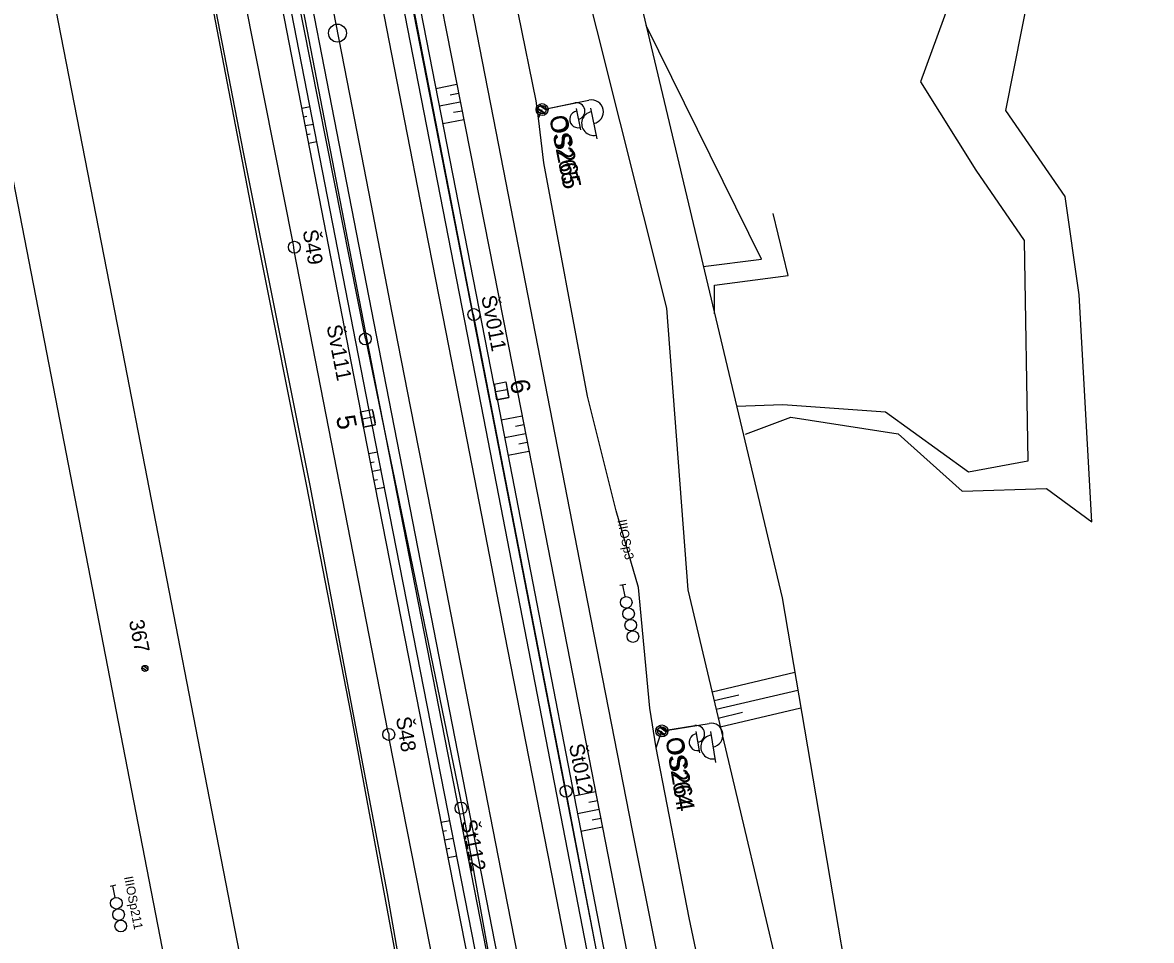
# Model space of a CAD drawing. Extents: x -545967 to -545044, y -1122650 to -1118491.
# Drawn here: x -545804.3 to -545710, y -1118963 to -1118886.3 of the extents above; entities that cross this region are included whole.
import ezdxf

# ---------------------------------------------------------------- set-up
doc = ezdxf.new("R2010")
doc.units = 0
for name, color, linetype in [('Vrstva 1', 7, 'Continuous'), ('Vrstva 1 - Koleje', 7, 'Continuous'), ('Vrstva 11', 7, 'Continuous'), ('Vrstva 11 - Trakce', 7, 'Continuous'), ('Vrstva 12 - Trakce zaklady', 7, 'Continuous'), ('Vrstva 19 - Staniceni', 7, 'Continuous'), ('Vrstva 25', 7, 'Continuous'), ('Vrstva 25 - silnoproud prvky', 7, 'Continuous'), ('Vrstva 26', 7, 'Continuous'), ('Vrstva 26 - silnoproud', 7, 'Continuous'), ('Vrstva 28 - zabzar', 7, 'Continuous'), ('Vrstva 32', 7, 'Continuous'), ('Vrstva 4 - Teren - stezky - prechody - plochy', 7, 'Continuous'), ('Vrstva 43', 7, 'Continuous'), ('Vrstva 44', 7, 'Continuous'), ('Vrstva 48', 7, 'Continuous'), ('Vrstva 49', 7, 'Continuous'), ('Vrstva 6', 7, 'Continuous'), ('Vrstva 62', 7, 'Continuous')]:
    doc.layers.add(name, color=color, linetype=linetype)

msp = doc.modelspace()

# ---------------------------------------------------------------- linework, layer by layer
at = {"layer": 'Vrstva 1'}
for points in [[(-545803.343, -1118697.361), (-545802.529, -1118701.559), (-545796.372, -1118733.137), (-545788.892, -1118771.626), (-545784.123, -1118796.192), (-545777.723, -1118829.089), (-545771.163, -1118862.699), (-545764.792, -1118895.381), (-545757.603, -1118932.309), (-545753.441, -1118953.648), (-545749.904, -1118971.286), (-545746.403, -1118987.4), (-545742.64, -1119003.664), (-545739.307, -1119017.411), (-545735.997, -1119030.103), (-545730.526, -1119049.438)], [(-545838.408, -1118714.766), (-545838.264, -1118718.348), (-545837.486, -1118728.28), (-545836.887, -1118733.389), (-545834.73, -1118746.875), (-545830.836, -1118767.188), (-545826.73, -1118788.319), (-545823.138, -1118806.831), (-545818.076, -1118832.894), (-545813.108, -1118858.452), (-545808.531, -1118881.987), (-545803.057, -1118910.121), (-545797.597, -1118938.248), (-545792.143, -1118966.396), (-545787.423, -1118990.652), (-545782.57, -1119015.553), (-545777.212, -1119042.997), (-545771.689, -1119071.297)], [(-545838.408, -1118714.766), (-545838.264, -1118718.348), (-545837.486, -1118728.28), (-545836.887, -1118733.389), (-545834.73, -1118746.875), (-545830.836, -1118767.188), (-545826.73, -1118788.319), (-545823.138, -1118806.831), (-545818.076, -1118832.894), (-545813.108, -1118858.452), (-545808.531, -1118881.987), (-545803.057, -1118910.121), (-545797.597, -1118938.248), (-545792.143, -1118966.396), (-545787.423, -1118990.652), (-545782.57, -1119015.553), (-545777.212, -1119042.997), (-545771.689, -1119071.297)], [(-545833.035, -1118722.987), (-545832.612, -1118725.218), (-545828.16, -1118748.155), (-545821.787, -1118781.064), (-545814.8, -1118816.973), (-545807.184, -1118856.232), (-545801.349, -1118886.259), (-545795.986, -1118913.812), (-545789.887, -1118945.221), (-545784.095, -1118975.016), (-545776.352, -1119014.883), (-545771.025, -1119042.195)]]:
    msp.add_lwpolyline(points, dxfattribs=at)
at = {"layer": 'Vrstva 1 - Koleje'}
for points in [[(-545789.005, -1118830.866), (-545787.094, -1118840.68), (-545785.112, -1118850.841), (-545782.605, -1118863.702), (-545780.708, -1118873.411), (-545778.842, -1118882.982), (-545777.033, -1118892.261), (-545775.242, -1118901.451), (-545773.471, -1118910.538), (-545771.912, -1118918.507), (-545770.23, -1118927.147), (-545768.195, -1118937.605), (-545766.358, -1118947.027), (-545764.382, -1118957.157), (-545762.439, -1118967.113)], [(-545783.856, -1118835.888), (-545781.902, -1118845.893), (-545780.09, -1118855.197), (-545779.231, -1118859.597), (-545777.534, -1118868.303), (-545775.637, -1118878.025), (-545773.736, -1118887.804), (-545771.983, -1118896.787), (-545770.701, -1118903.363), (-545768.985, -1118912.147), (-545767.842, -1118918.004), (-545766.003, -1118927.456), (-545764.066, -1118937.395), (-545762.038, -1118947.792), (-545760.159, -1118957.414), (-545758.172, -1118967.592)]]:
    msp.add_lwpolyline(points, dxfattribs=at)
at = {"layer": 'Vrstva 11'}
for p, q in [((-545793.97, -1118940.46), (-545794.348, -1118940.204)), ((-545793.862, -1118940.306), (-545794.246, -1118940.047))]:
    msp.add_line(p, q, dxfattribs=at)
msp.add_circle((-545794.104, -1118940.251), 0.25, dxfattribs=at)
at = {"layer": 'Vrstva 11 - Trakce'}
for p, q in [((-545763.943, -1118916.485), (-545763.763, -1118917.469)), ((-545764.927, -1118916.665), (-545764.747, -1118917.649)), ((-545763.853, -1118916.977), (-545764.837, -1118917.157)), ((-545776.046, -1118918.952), (-545775.85, -1118919.932)), ((-545774.968, -1118919.246), (-545775.948, -1118919.442)), ((-545775.066, -1118918.756), (-545774.87, -1118919.736))]:
    msp.add_line(p, q, dxfattribs=at)
at = {"layer": 'Vrstva 12 - Trakce zaklady'}
for p, q in [((-545764.942, -1118916.501), (-545763.958, -1118916.32)), ((-545764.703, -1118917.803), (-545763.719, -1118917.622)), ((-545776.104, -1118918.814), (-545775.123, -1118918.618)), ((-545775.848, -1118920.094), (-545774.867, -1118919.898))]:
    msp.add_line(p, q, dxfattribs=at)
for points in [[(-545764.703, -1118917.803), (-545764.942, -1118916.501), (-545763.958, -1118916.32), (-545763.719, -1118917.622), (-545764.703, -1118917.803)], [(-545764.942, -1118916.501), (-545764.942, -1118916.501), (-545764.703, -1118917.803), (-545764.703, -1118917.803)], [(-545775.123, -1118918.618), (-545774.867, -1118919.898), (-545775.848, -1118920.094), (-545776.104, -1118918.814), (-545775.123, -1118918.618)], [(-545776.104, -1118918.814), (-545776.104, -1118918.814), (-545775.848, -1118920.094), (-545775.848, -1118920.094)], [(-545775.123, -1118918.618), (-545775.123, -1118918.618), (-545774.867, -1118919.898), (-545774.867, -1118919.898)]]:
    msp.add_lwpolyline(points, dxfattribs=at)
at = {"layer": 'Vrstva 19 - Staniceni'}
msp.add_circle((-545778.025, -1118887.174), 0.75, dxfattribs=at)
at = {"layer": 'Vrstva 25'}
for p, q in [((-545760.45, -1118893.462), (-545757.021, -1118892.763)), ((-545761.416, -1118893.415), (-545760.617, -1118893.943)), ((-545761.179, -1118893.123), (-545760.445, -1118893.608)), ((-545756.881, -1118893.449), (-545756.362, -1118895.997)), ((-545750.441, -1118945.401), (-545746.986, -1118944.844)), ((-545751.404, -1118945.315), (-545750.628, -1118945.875)), ((-545751.155, -1118945.032), (-545750.442, -1118945.547)), ((-545746.875, -1118945.536), (-545746.461, -1118948.102))]:
    msp.add_line(p, q, dxfattribs=at)
for centre in [(-545760.94, -1118893.562), (-545760.94, -1118893.562), (-545750.935, -1118945.481), (-545750.935, -1118945.481)]:
    msp.add_circle(centre, 0.5, dxfattribs=at)
for centre, start, end in [((-545756.821, -1118893.743), 281.52003, 101.52003), ((-545756.633, -1118894.725), 100.81745, 282.2226), ((-545746.827, -1118945.832), 279.15692, 99.15692), ((-545746.68, -1118946.821), 98.45434, 279.85949)]:
    msp.add_arc(centre, 1, start, end, dxfattribs=at)
at = {"layer": 'Vrstva 25 - silnoproud prvky'}
for p, q in [((-545760.597, -1118893.492), (-545758.196, -1118893.003)), ((-545761.273, -1118893.459), (-545760.714, -1118893.829)), ((-545761.107, -1118893.255), (-545760.593, -1118893.594)), ((-545758.099, -1118893.483), (-545757.735, -1118895.266)), ((-545751.264, -1118945.365), (-545750.72, -1118945.757)), ((-545751.089, -1118945.167), (-545750.59, -1118945.527)), ((-545750.589, -1118945.425), (-545748.171, -1118945.035)), ((-545748.093, -1118945.519), (-545747.803, -1118947.316))]:
    msp.add_line(p, q, dxfattribs=at)
for centre in [(-545760.94, -1118893.562), (-545750.935, -1118945.481)]:
    msp.add_circle(centre, 0.35, dxfattribs=at)
for centre, start, end in [((-545758.057, -1118893.689), 281.52003, 101.52003), ((-545757.925, -1118894.376), 100.81745, 282.2226), ((-545747.956, -1118946.419), 98.45434, 279.85949), ((-545748.059, -1118945.726), 279.15692, 99.15692)]:
    msp.add_arc(centre, 0.7, start, end, dxfattribs=at)
at = {"layer": 'Vrstva 26'}
for points in [[(-545746.037, -1118973.539), (-545748.64, -1118961.097), (-545751.402, -1118946.894), (-545751.937, -1118943.575), (-545752.873, -1118933.506), (-545754.741, -1118927.082), (-545757.146, -1118917.51), (-545760.799, -1118898.018), (-545761.246, -1118894.282), (-545761.421, -1118892.823), (-545762.895, -1118885.591), (-545764.903, -1118877.023), (-545767.229, -1118863.082), (-545767.317, -1118860.995), (-545767.592, -1118859.454), (-545769.02, -1118853.189), (-545770.747, -1118842.19), (-545771.097, -1118840.383), (-545773.141, -1118830.925)], [(-545761.246, -1118894.282), (-545760.94, -1118893.562)], [(-545751.402, -1118946.894), (-545750.935, -1118945.481)]]:
    msp.add_lwpolyline(points, dxfattribs=at)
at = {"layer": 'Vrstva 26 - silnoproud'}
for points in [[(-545800.897, -1118821.514), (-545796.684, -1118843.318), (-545791.187, -1118870.631), (-545788.655, -1118883.96), (-545784.722, -1118904.395), (-545780.641, -1118924.894), (-545776.901, -1118944.085), (-545772.527, -1118967.671), (-545767.712, -1118991.461), (-545763.383, -1119013.326), (-545759.751, -1119031.811), (-545755.576, -1119054.337), (-545752.321, -1119069.685), (-545748.72, -1119088.787), (-545745.498, -1119105.777)], [(-545746.037, -1118973.539), (-545748.64, -1118961.097), (-545751.402, -1118946.894), (-545751.937, -1118943.575), (-545752.873, -1118933.506), (-545754.741, -1118927.082), (-545757.146, -1118917.51), (-545760.799, -1118898.018), (-545761.246, -1118894.282), (-545761.421, -1118892.823), (-545762.895, -1118885.591), (-545764.903, -1118877.023), (-545767.229, -1118863.082), (-545767.317, -1118860.995), (-545767.592, -1118859.454), (-545769.02, -1118853.189), (-545770.747, -1118842.19), (-545771.097, -1118840.383), (-545773.141, -1118830.925)], [(-545761.246, -1118894.282), (-545760.94, -1118893.562)], [(-545751.402, -1118946.894), (-545750.935, -1118945.481)]]:
    msp.add_lwpolyline(points, dxfattribs=at)
at = {"layer": 'Vrstva 28 - zabzar'}
msp.add_lwpolyline([(-545759.72, -1119031.91), (-545759.89, -1119030.77), (-545763.23, -1119013.33), (-545766.25, -1118997.62), (-545768.86, -1118984.55), (-545771, -1118974.69), (-545771.8, -1118970.9), (-545773.86, -1118959.07), (-545776.3, -1118946.17), (-545780.31, -1118924.98), (-545785.87, -1118897.11), (-545790.99, -1118870.65), (-545796.29, -1118843.25), (-545799.19, -1118827.63), (-545805.85, -1118794.17), (-545808.2, -1118783.5), (-545812.82, -1118758.82), (-545816.62, -1118739.16), (-545820.43, -1118719.58), (-545822.89, -1118707.67), (-545825.23, -1118696.09)], dxfattribs=at)
at = {"layer": 'Vrstva 32'}
msp.add_lwpolyline([(-545746.9, -1119097.66), (-545750.31, -1119079.79), (-545751.4, -1119074.13), (-545752.97, -1119065.38), (-545755.29, -1119054.49), (-545758.65, -1119036.78), (-545759.72, -1119031.91), (-545759.89, -1119030.77), (-545763.23, -1119013.33), (-545766.25, -1118997.62), (-545768.86, -1118984.55), (-545771, -1118974.69), (-545771.8, -1118970.9), (-545773.86, -1118959.07), (-545776.3, -1118946.17), (-545780.31, -1118924.98), (-545785.87, -1118897.11), (-545790.99, -1118870.65), (-545796.29, -1118843.25), (-545799.19, -1118827.63)], dxfattribs=at)
at = {"layer": 'Vrstva 4 - Teren - stezky - prechody - plochy'}
for points in [[(-545842.991, -1118523.919), (-545841.705, -1118530.396), (-545836.849, -1118554.447), (-545831.054, -1118584.604), (-545819.351, -1118645.264), (-545811.232, -1118686.911), (-545799.532, -1118746.647), (-545788.535, -1118802.768), (-545777.847, -1118857.696), (-545765.826, -1118919.341), (-545755.98, -1118970.183), (-545745.509, -1119023.121), (-545734.813, -1119078.883), (-545723.148, -1119138.675), (-545711.327, -1119199.256), (-545707.51, -1119218.932), (-545706.355, -1119218.803)], [(-545710.225, -1119247.22), (-545719.004, -1119201.386), (-545730.622, -1119141.385), (-545736.208, -1119112.206), (-545742.564, -1119078.927), (-545753.414, -1119021.814), (-545763.359, -1118970.942), (-545773.922, -1118916.709), (-545785.328, -1118858.188), (-545796.206, -1118802.914), (-545806.845, -1118748.63), (-545819.206, -1118686.191), (-545827.818, -1118641.013), (-545849.345, -1118530.249), (-545850.409, -1118525.371)], [(-545711.324, -1119247.435), (-545711.901, -1119243.963), (-545720.224, -1119201.665), (-545721.285, -1119195.757), (-545731.546, -1119141.712), (-545737.081, -1119112.42), (-545743.441, -1119079.103), (-545754.278, -1119022.005), (-545764.127, -1118971.243), (-545774.702, -1118917.119), (-545786.098, -1118858.181), (-545797.005, -1118803.413), (-545807.661, -1118749.422), (-545819.911, -1118686.431), (-545828.531, -1118641.36), (-545850.15, -1118530.525), (-545851.156, -1118525.517)], [(-545787.709, -1118802.92), (-545777.141, -1118857.583), (-545765.122, -1118918.891), (-545755.123, -1118970.549), (-545744.471, -1119024.933), (-545734.117, -1119078.34), (-545722.331, -1119138.405), (-545711.219, -1119196.145), (-545707.543, -1119214.266), (-545707.412, -1119215.197), (-545706.355, -1119218.803)]]:
    msp.add_lwpolyline(points, dxfattribs=at)
at = {"layer": 'Vrstva 43'}
for centre in [(-545781.627, -1118905.062), (-545766.628, -1118910.692), (-545775.699, -1118912.728), (-545773.737, -1118945.768), (-545758.937, -1118950.523), (-545767.698, -1118951.929)]:
    msp.add_circle(centre, 0.5, dxfattribs=at)
at = {"layer": 'Vrstva 44'}
for points in [[(-545799.29, -1118815.321), (-545789.933, -1118863.748), (-545789.78, -1118864.001), (-545789.769, -1118864.308), (-545781.742, -1118904.714), (-545781.69, -1118905.058), (-545781.683, -1118905.37), (-545773.843, -1118945.459), (-545773.731, -1118945.723), (-545773.748, -1118946.113), (-545765.823, -1118986.247), (-545765.769, -1118986.707), (-545765.632, -1118987.212), (-545755.037, -1119039.456), (-545755.013, -1119039.882), (-545755.034, -1119040.218), (-545744.158, -1119093.432), (-545744.096, -1119093.785), (-545744.065, -1119094.166), (-545734.822, -1119146.139)], [(-545766.704, -1118910.666), (-545776.282, -1118861.269)], [(-545775.683, -1118912.677), (-545785.44, -1118863.505), (-545785.429, -1118863.254)], [(-545766.704, -1118910.666), (-545758.96, -1118950.56), (-545752.526, -1118984.222), (-545761.24, -1118985.732), (-545761.568, -1118985.764)], [(-545775.683, -1118912.677), (-545767.609, -1118951.877), (-545761.581, -1118985.483), (-545761.568, -1118985.764)]]:
    msp.add_lwpolyline(points, dxfattribs=at)
at = {"layer": 'Vrstva 48'}
for p, q in [((-545768.055, -1118891.474), (-545769.805, -1118891.818)), ((-545767.765, -1118892.945), (-545769.517, -1118893.29)), ((-545767.91, -1118892.209), (-545768.611, -1118892.347)), ((-545781.006, -1118893.433), (-545780.313, -1118893.298)), ((-545767.62, -1118893.681), (-545768.322, -1118893.819)), ((-545780.863, -1118894.169), (-545780.586, -1118894.115)), ((-545780.72, -1118894.905), (-545780.026, -1118894.77)), ((-545767.476, -1118894.417), (-545769.229, -1118894.762)), ((-545780.577, -1118895.641), (-545780.299, -1118895.587)), ((-545780.434, -1118896.378), (-545779.739, -1118896.243)), ((-545762.608, -1118919.179), (-545764.342, -1118919.519)), ((-545762.464, -1118919.915), (-545763.158, -1118920.051)), ((-545762.32, -1118920.651), (-545764.057, -1118920.991)), ((-545775.402, -1118922.311), (-545774.688, -1118922.171)), ((-545762.032, -1118922.123), (-545763.772, -1118922.464)), ((-545762.176, -1118921.387), (-545762.871, -1118921.523)), ((-545775.258, -1118923.047), (-545774.972, -1118922.991)), ((-545775.113, -1118923.783), (-545774.398, -1118923.642)), ((-545774.969, -1118924.519), (-545774.683, -1118924.463)), ((-545774.824, -1118925.255), (-545774.109, -1118925.114)), ((-545746.739, -1118942.209), (-545739.834, -1118940.578)), ((-545746.395, -1118943.669), (-545739.582, -1118942.06)), ((-545746.567, -1118942.939), (-545744.509, -1118942.453)), ((-545746.222, -1118944.399), (-545744.192, -1118943.92)), ((-545746.05, -1118945.129), (-545739.33, -1118943.541)), ((-545756.465, -1118950.574), (-545758.265, -1118950.926)), ((-545756.321, -1118951.31), (-545757.042, -1118951.451)), ((-545756.177, -1118952.046), (-545757.98, -1118952.399)), ((-545769.357, -1118953.111), (-545768.638, -1118952.97)), ((-545756.033, -1118952.782), (-545756.755, -1118952.923)), ((-545769.212, -1118953.847), (-545768.925, -1118953.791)), ((-545755.889, -1118953.518), (-545757.695, -1118953.871)), ((-545769.068, -1118954.583), (-545768.349, -1118954.442)), ((-545768.923, -1118955.319), (-545768.636, -1118955.263)), ((-545768.779, -1118956.055), (-545768.06, -1118955.914))]:
    msp.add_line(p, q, dxfattribs=at)
at = {"layer": 'Vrstva 49'}
for points in [[(-545839.308, -1118523.198), (-545838.102, -1118529.579), (-545837.4, -1118533.485), (-545832.706, -1118555.695), (-545825.144, -1118594.377), (-545814.251, -1118651.352), (-545808.026, -1118685.152), (-545795.162, -1118750.192), (-545783.943, -1118809.71), (-545774.848, -1118856.951), (-545763.418, -1118915.038), (-545752.928, -1118968.655), (-545741.707, -1119025.946), (-545730.219, -1119081.986), (-545719.001, -1119141.326), (-545708.857, -1119196.833), (-545704.642, -1119214.146)], [(-545790.558, -1118698.682), (-545783.238, -1118737.17), (-545773.95, -1118795.15), (-545740.894, -1118934.351)], [(-545795.7, -1118699.528), (-545788.233, -1118737.742), (-545783.17, -1118774.198), (-545777.676, -1118791.958), (-545766.252, -1118834.896), (-545762.229, -1118863.517), (-545750.538, -1118910.15), (-545748.755, -1118933.679), (-545738.226, -1118978.242), (-545734.453, -1118993.366), (-545726.802, -1119029.271), (-545708.682, -1119069.733), (-545699.17, -1119099.963), (-545685.313, -1119124.181), (-545683.358, -1119136.056), (-545688.074, -1119145.796), (-545688.341, -1119153.091)], [(-545785.57, -1118809.023), (-545776.461, -1118857.744), (-545776.223, -1118859.028), (-545764.986, -1118916.441), (-545764.658, -1118917.886), (-545754.446, -1118970.66), (-545754.175, -1118971.989), (-545744.319, -1119022.631), (-545744.059, -1119023.95), (-545733.435, -1119078.425), (-545721.625, -1119138.52), (-545721.391, -1119139.742), (-545710.151, -1119197.125), (-545709.969, -1119198.727), (-545706.792, -1119214.135), (-545707.412, -1119215.197), (-545706.355, -1119218.803), (-545705.856, -1119218.828), (-545705.109, -1119218.756), (-545703.505, -1119218.63), (-545703.071, -1119219.321), (-545701.68, -1119223.926)], [(-545712.345, -1119247.635), (-545712.918, -1119244.626), (-545721.552, -1119201.108), (-545732.642, -1119141.942), (-545733.194, -1119140.665), (-545738.437, -1119113.17), (-545744.258, -1119082.787), (-545744.781, -1119080.348), (-545754.155, -1119031.651), (-545755.213, -1119026.18), (-545765.268, -1118974.147), (-545765.5, -1118972.759), (-545775.821, -1118920.177), (-545776.085, -1118918.771), (-545787.25, -1118861.285), (-545787.565, -1118859.78), (-545796.822, -1118811.001)], [(-545711.324, -1119247.435), (-545711.901, -1119243.963), (-545720.224, -1119201.665), (-545721.285, -1119195.757), (-545721.943, -1119195.521), (-545732.082, -1119141.82), (-545732.265, -1119140.515), (-545737.739, -1119112.717), (-545743.315, -1119083.132), (-545744.039, -1119079.561), (-545753.263, -1119031.334), (-545754.002, -1119028.935), (-545754.148, -1119025.929), (-545754.487, -1119024.319), (-545754.825, -1119024.298), (-545764.544, -1118973.992), (-545764.787, -1118972.577), (-545775.108, -1118920.03), (-545775.396, -1118918.541), (-545786.585, -1118861.093), (-545786.924, -1118859.548), (-545796.323, -1118810.897)], [(-545740.894, -1118934.351), (-545731.052, -1118992.184), (-545723.951, -1119028.164), (-545702.926, -1119068.123), (-545693.558, -1119095.87)]]:
    msp.add_lwpolyline(points, dxfattribs=at)
at = {"layer": 'Vrstva 6'}
for p, q in [((-545753.94, -1118933.239), (-545754.431, -1118933.334)), ((-545753.996, -1118934.258), (-545754.185, -1118933.287)), ((-545796.529, -1118958.374), (-545797.02, -1118958.469)), ((-545796.585, -1118959.393), (-545796.774, -1118958.422))]:
    msp.add_line(p, q, dxfattribs=at)
for centre in [(-545753.903, -1118934.735), (-545753.717, -1118935.688), (-545753.531, -1118936.641), (-545753.346, -1118937.594), (-545796.492, -1118959.87), (-545796.306, -1118960.823), (-545796.12, -1118961.776)]:
    msp.add_circle(centre, 0.486, dxfattribs=at)
at = {"layer": 'Vrstva 62'}
for points in [[(-545664.463, -1118863.447), (-545693.262, -1118857.214), (-545700.931, -1118857.806), (-545697.393, -1118860.918), (-545700.447, -1118865.244), (-545702.583, -1118858.209), (-545708.513, -1118858.418), (-545717.149, -1118863.96), (-545722.289, -1118871.935), (-545729.33, -1118891.244), (-545724.714, -1118898.613), (-545720.665, -1118904.502), (-545720.365, -1118922.929), (-545725.31, -1118923.845), (-545732.264, -1118918.838), (-545740.824, -1118918.226), (-545744.688, -1118918.372)], [(-545743.949, -1118920.691), (-545740.17, -1118919.261), (-545731.195, -1118920.647), (-545725.86, -1118925.431), (-545718.8, -1118925.214), (-545715.03, -1118928.012), (-545716.07, -1118909.035), (-545717.246, -1118900.828), (-545722.2, -1118893.635), (-545718.125, -1118872.969), (-545714.047, -1118865.665), (-545703.814, -1118860.205), (-545702.609, -1118870.651), (-545693.99, -1118863.27), (-545684.832, -1118860.545), (-545664.047, -1118865.281)], [(-545747.489, -1118906.673), (-545742.623, -1118906.064), (-545752.249, -1118886.533)], [(-545746.525, -1118910.637), (-545746.525, -1118908.219), (-545740.39, -1118907.414), (-545741.65, -1118902.244)]]:
    msp.add_lwpolyline(points, dxfattribs=at)

# ---------------------------------------------------------------- texts
at = {"layer": 'Vrstva 11'}
msp.add_text('367', height=1.25, rotation=280.98894, dxfattribs=at).set_placement((-545795.448, -1118936.294))
at = {"layer": 'Vrstva 11 - Trakce'}
for s, rotation, p in [('6', 280.40163, (-545763.632, -1118916.246)), ('5', 281.30993, (-545778.16, -1118919.245))]:
    msp.add_text(s, height=1.6, rotation=rotation, dxfattribs=at).set_placement(p)
at = {"layer": 'Vrstva 25'}
for s, rotation, p in [('OS265', 281.52003, (-545760.35, -1118894.185)), ('OS264', 279.15692, (-545750.635, -1118946.114))]:
    msp.add_text(s, height=1.5, rotation=rotation, dxfattribs=at).set_placement(p)
at = {"layer": 'Vrstva 25 - silnoproud prvky'}
for s, rotation, p in [('OS265', 281.52003, (-545760.35, -1118894.185)), ('OS264', 279.15692, (-545750.635, -1118946.114))]:
    msp.add_text(s, height=1.4, rotation=rotation, dxfattribs=at).set_placement(p)
at = {"layer": 'Vrstva 43'}
for s, rotation, p in [('Š49', 279.31701, (-545780.93, -1118903.679)), ('Šv011', 280.99979, (-545766.025, -1118909.193)), ('Šv111', 280.99979, (-545778.943, -1118911.649)), ('Š48', 279.31701, (-545773.144, -1118944.377)), ('Št012', 280.99979, (-545758.703, -1118946.658)), ('Št112', 280.99979, (-545767.672, -1118953.006))]:
    msp.add_text(s, height=1.25, rotation=rotation, dxfattribs=at).set_placement(p)
at = {"layer": 'Vrstva 6'}
for s, rotation, p in [('IIIOSp3', 281.03652, (-545754.64, -1118927.883)), ('IIIOSp211', 280.96583, (-545795.852, -1118957.691))]:
    msp.add_text(s, height=0.75, rotation=rotation, dxfattribs=at).set_placement(p)

doc.saveas('drawing.dxf')
